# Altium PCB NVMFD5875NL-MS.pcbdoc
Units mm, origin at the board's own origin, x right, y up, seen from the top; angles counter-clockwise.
Board outline 19.72 x 18.2 mm, 2 copper layers (Top Layer, Bottom Layer), stack 0 mm thick; 1 components, 0 nets, 6 pads, 0 vias.
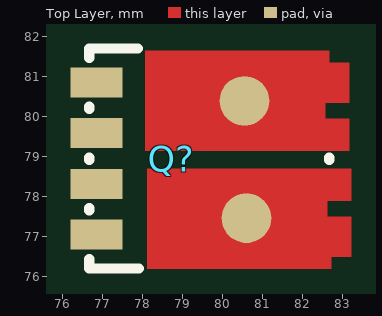
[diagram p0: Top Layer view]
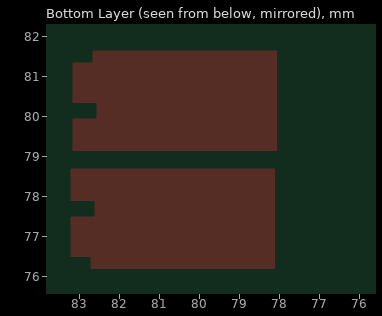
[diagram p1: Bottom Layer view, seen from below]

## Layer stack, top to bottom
Top Layer: signal copper (thickness not stored)
Bottom Layer: signal copper (thickness not stored)

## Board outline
89.57,69.85 69.85,69.85 69.85,88.05 89.57,88.05

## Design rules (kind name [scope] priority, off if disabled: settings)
PasteMaskExpansion "Paste Mask Expansion" [All] p1: expansion=0
SolderMaskExpansion "Solder Mask Expansion" [IsVia] p1: expansion=-25.4 istentingtop=TRUE
SolderMaskExpansion "Solder Mask Expansion" [All] p2: expansion=0.051 istentingtop=FALSE

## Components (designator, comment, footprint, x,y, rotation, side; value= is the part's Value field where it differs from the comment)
Q? "NVMFD5875NL-MS" TDSON-8-4_IPG20N06S4L26 78.76,78.95 r0 top

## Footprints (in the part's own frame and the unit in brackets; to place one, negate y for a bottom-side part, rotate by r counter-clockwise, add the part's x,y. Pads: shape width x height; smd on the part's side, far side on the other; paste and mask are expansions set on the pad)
TDSON-8-4_IPG20N06S4L26 [mil]
  rect 51.2x29.5 smd: 1(-75.18,75) 2(-75.18,25) 3(-75.18,-25) 4(-75.18,-75)
  round 48.88 smd: 5(72.37,-58.72) 6(70.4,56.75)
  Top Layer region: -27.18,106.3 153.93,106.3 153.93,94.49 173.61,94.49 173.61,55.12 149.99,55.12 149.99,39.37 173.61,39.37 173.61,7.87 -27.18,7.87
  Top Layer region: -25.21,-108.27 155.89,-108.27 155.89,-96.46 175.58,-96.46 175.58,-57.09 151.96,-57.09 151.96,-41.34 175.58,-41.34 175.58,-9.84 -25.21,-9.84
  silkscreen extent -82,-108 154,108

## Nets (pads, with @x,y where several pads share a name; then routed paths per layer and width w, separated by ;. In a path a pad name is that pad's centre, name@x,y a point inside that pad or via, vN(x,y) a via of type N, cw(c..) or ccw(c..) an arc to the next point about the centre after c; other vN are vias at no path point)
pads on no net: Q?.1 Q?.2 Q?.3 Q?.4 Q?.5 Q?.6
